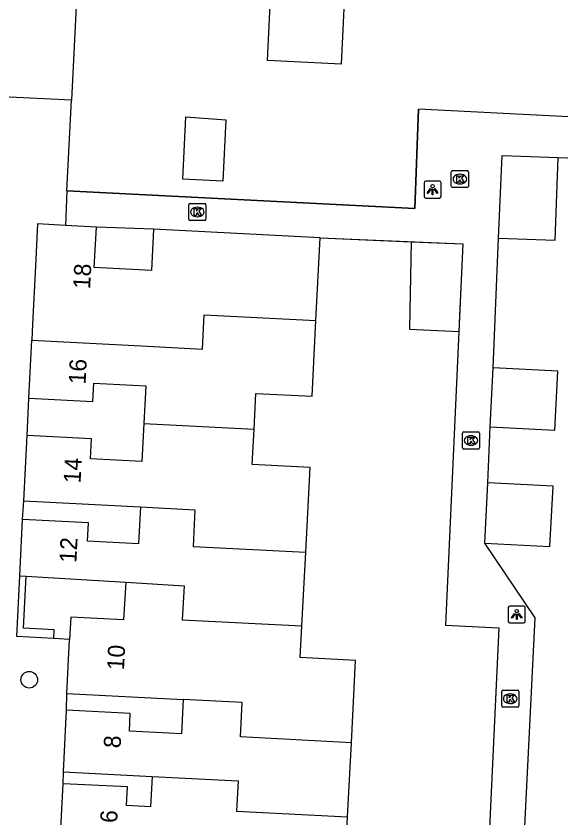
# Model space of a CAD drawing. Extents: x 162990 to 165007, y 383433 to 384336.
# Drawn here: x 164464.46 to 164496.47, y 383792.95 to 383840 of the extents above; entities that cross this region are included whole.
import ezdxf

# ---------------------------------------------------------------- set-up
doc = ezdxf.new("R2010")
doc.units = 0
for name, color, linetype in [('IMGEO_Boom', 7, 'Continuous'), ('IMGEO_Kolk', 7, 'Continuous'), ('IMGEO_Lichtpunt', 7, 'Continuous'), ('IMGEO_Muur', 7, 'Continuous'), ('IMGEO_Pand', 7, 'Continuous'), ('IMGEO_Pand_nummerreeks', 7, 'Continuous'), ('IMGEO_Voetpad_open', 7, 'Continuous')]:
    doc.layers.add(name, color=color, linetype=linetype)

msp = doc.modelspace()

# ---------------------------------------------------------------- linework, layer by layer
at = {"layer": 'IMGEO_Boom'}
msp.add_circle((164465.239, 383801.064), 0.489, dxfattribs=at)
at = {"layer": 'IMGEO_Kolk'}
for p, q in [((164490.028, 383830.011), (164490.028, 383830.863)), ((164490.103, 383830.937), (164490.955, 383830.937)), ((164491.029, 383830.863), (164491.029, 383830.011)), ((164490.516, 383830.717), (164490.541, 383830.717)), ((164490.955, 383829.937), (164490.103, 383829.937)), ((164490.539, 383830.157), (164490.514, 383830.157)), ((164474.612, 383828.079), (164474.612, 383828.931)), ((164474.687, 383829.005), (164475.539, 383829.005)), ((164475.613, 383828.931), (164475.613, 383828.079)), ((164475.1, 383828.785), (164475.125, 383828.785)), ((164475.539, 383828.005), (164474.687, 383828.005)), ((164475.123, 383828.225), (164475.098, 383828.225)), ((164490.682, 383814.674), (164490.682, 383815.526)), ((164490.757, 383815.6), (164491.609, 383815.6)), ((164491.17, 383815.38), (164491.195, 383815.38)), ((164491.683, 383815.526), (164491.683, 383814.674)), ((164491.193, 383814.82), (164491.168, 383814.82)), ((164491.609, 383814.6), (164490.757, 383814.6)), ((164492.987, 383799.523), (164492.987, 383800.375)), ((164493.062, 383800.449), (164493.914, 383800.449)), ((164493.475, 383800.229), (164493.5, 383800.229)), ((164493.988, 383800.375), (164493.988, 383799.523)), ((164493.914, 383799.449), (164493.062, 383799.449)), ((164493.498, 383799.669), (164493.473, 383799.669))]:
    msp.add_line(p, q, dxfattribs=at)
for points in [[(164490.028, 383830.011), (164490.028, 383830.863)], [(164490.103, 383830.937), (164490.955, 383830.937)], [(164491.029, 383830.863), (164491.029, 383830.011)], [(164490.349, 383830.637), (164490.472, 383830.637), (164490.472, 383830.486), (164490.602, 383830.637), (164490.766, 383830.637), (164490.62, 383830.486), (164490.773, 383830.237), (164490.621, 383830.237), (164490.536, 383830.401), (164490.472, 383830.334), (164490.472, 383830.237), (164490.349, 383830.237), (164490.349, 383830.637)], [(164490.955, 383829.937), (164490.103, 383829.937)], [(164474.612, 383828.079), (164474.612, 383828.931)], [(164474.687, 383829.005), (164475.539, 383829.005)], [(164475.613, 383828.931), (164475.613, 383828.079)], [(164474.933, 383828.705), (164475.056, 383828.705), (164475.056, 383828.554), (164475.186, 383828.705), (164475.35, 383828.705), (164475.204, 383828.554), (164475.357, 383828.305), (164475.205, 383828.305), (164475.12, 383828.469), (164475.056, 383828.402), (164475.056, 383828.305), (164474.933, 383828.305), (164474.933, 383828.705)], [(164475.539, 383828.005), (164474.687, 383828.005)], [(164490.682, 383814.674), (164490.682, 383815.526)], [(164490.757, 383815.6), (164491.609, 383815.6)], [(164491.003, 383815.3), (164491.126, 383815.3), (164491.126, 383815.149), (164491.256, 383815.3), (164491.42, 383815.3), (164491.274, 383815.149), (164491.427, 383814.9), (164491.275, 383814.9), (164491.19, 383815.064), (164491.126, 383814.997), (164491.126, 383814.9), (164491.003, 383814.9), (164491.003, 383815.3)], [(164491.683, 383815.526), (164491.683, 383814.674)], [(164491.609, 383814.6), (164490.757, 383814.6)], [(164492.987, 383799.523), (164492.987, 383800.375)], [(164493.062, 383800.449), (164493.914, 383800.449)], [(164493.988, 383800.375), (164493.988, 383799.523)], [(164493.308, 383800.149), (164493.431, 383800.149), (164493.431, 383799.998), (164493.561, 383800.149), (164493.725, 383800.149), (164493.579, 383799.998), (164493.732, 383799.749), (164493.58, 383799.749), (164493.495, 383799.913), (164493.431, 383799.846), (164493.431, 383799.749), (164493.308, 383799.749), (164493.308, 383800.149)], [(164493.914, 383799.449), (164493.062, 383799.449)]]:
    msp.add_lwpolyline(points, dxfattribs=at)
for centre, start, end in [((164490.105, 383830.861), 91.552, 178.448), ((164490.105, 383830.861), 91.552, 178.448), ((164490.953, 383830.861), 1.552, 88.448), ((164490.953, 383830.861), 1.552, 88.448), ((164490.105, 383830.013), 181.552, 268.448), ((164490.105, 383830.013), 181.552, 268.448), ((164490.953, 383830.013), 271.552, 358.448), ((164490.953, 383830.013), 271.552, 358.448), ((164474.689, 383828.929), 91.552, 178.448), ((164474.689, 383828.929), 91.552, 178.448), ((164475.537, 383828.929), 1.552, 88.448), ((164475.537, 383828.929), 1.552, 88.448), ((164474.689, 383828.081), 181.552, 268.448), ((164474.689, 383828.081), 181.552, 268.448), ((164475.537, 383828.081), 271.552, 358.448), ((164475.537, 383828.081), 271.552, 358.448), ((164490.759, 383815.524), 91.552, 178.448), ((164490.759, 383815.524), 91.552, 178.448), ((164491.607, 383815.524), 1.552, 88.448), ((164491.607, 383815.524), 1.552, 88.448), ((164490.759, 383814.676), 181.552, 268.448), ((164490.759, 383814.676), 181.552, 268.448), ((164491.607, 383814.676), 271.552, 358.448), ((164491.607, 383814.676), 271.552, 358.448), ((164493.064, 383800.373), 91.552, 178.448), ((164493.064, 383800.373), 91.552, 178.448), ((164493.912, 383800.373), 1.552, 88.448), ((164493.912, 383800.373), 1.552, 88.448), ((164493.064, 383799.525), 181.552, 268.448), ((164493.064, 383799.525), 181.552, 268.448), ((164493.912, 383799.525), 271.552, 358.448), ((164493.912, 383799.525), 271.552, 358.448)]:
    msp.add_arc(centre, 0.0765, start, end, dxfattribs=at)
for centre, major_axis, ratio, start_param, end_param in [((164490.515, 383830.437), (-0.387, 0.002), 0.722429, 4.712389, 7.853982), ((164490.54, 383830.437), (-0.39, 0.002), 0.717154, 1.570796, 4.712389), ((164475.099, 383828.505), (-0.387, 0.002), 0.722429, 4.712389, 7.853982), ((164475.124, 383828.505), (-0.39, 0.002), 0.717154, 1.570796, 4.712389), ((164491.169, 383815.1), (-0.387, 0.002), 0.722429, 4.712389, 7.853982), ((164491.194, 383815.1), (-0.39, 0.002), 0.717154, 1.570796, 4.712389), ((164493.474, 383799.949), (-0.387, 0.002), 0.722429, 4.712389, 7.853982), ((164493.499, 383799.949), (-0.39, 0.002), 0.717154, 1.570796, 4.712389)]:
    msp.add_ellipse(centre, major_axis=major_axis, ratio=ratio, start_param=start_param, end_param=end_param, dxfattribs=at)
at = {"layer": 'IMGEO_Lichtpunt'}
for p, q in [((164488.427, 383830.225), (164488.427, 383829.418)), ((164488.427, 383830.225), (164488.427, 383829.418)), ((164489.329, 383830.32), (164488.521, 383830.32)), ((164489.329, 383830.32), (164488.521, 383830.32)), ((164489.423, 383829.418), (164489.423, 383830.225)), ((164489.423, 383829.418), (164489.423, 383830.225)), ((164488.521, 383829.324), (164489.329, 383829.324)), ((164488.521, 383829.324), (164489.329, 383829.324)), ((164493.372, 383805.294), (164493.372, 383804.487)), ((164493.372, 383805.294), (164493.372, 383804.487)), ((164494.274, 383805.389), (164493.466, 383805.389)), ((164494.274, 383805.389), (164493.466, 383805.389)), ((164494.368, 383804.487), (164494.368, 383805.294)), ((164494.368, 383804.487), (164494.368, 383805.294)), ((164493.466, 383804.393), (164494.274, 383804.393)), ((164493.466, 383804.393), (164494.274, 383804.393))]:
    msp.add_line(p, q, dxfattribs=at)
for points in [[(164488.801, 383829.889), (164488.84, 383829.861), (164488.652, 383829.599), (164488.614, 383829.626), (164488.801, 383829.889)], [(164489.013, 383829.861), (164489.051, 383829.888), (164489.238, 383829.626), (164489.199, 383829.598), (164489.013, 383829.861)], [(164488.903, 383829.841), (164488.95, 383829.841), (164488.95, 383829.519), (164488.903, 383829.519), (164488.903, 383829.841)], [(164493.746, 383804.958), (164493.785, 383804.93), (164493.597, 383804.668), (164493.559, 383804.695), (164493.746, 383804.958)], [(164493.958, 383804.93), (164493.996, 383804.957), (164494.183, 383804.695), (164494.144, 383804.667), (164493.958, 383804.93)], [(164493.848, 383804.91), (164493.895, 383804.91), (164493.895, 383804.588), (164493.848, 383804.588), (164493.848, 383804.91)]]:
    msp.add_lwpolyline(points, dxfattribs=at)
for centre in [(164488.926, 383830.023), (164493.871, 383805.092)]:
    msp.add_circle(centre, 0.0994, dxfattribs=at)
for centre, start, end in [((164488.521, 383830.225), 90, 180), ((164488.521, 383830.225), 90, 180), ((164489.329, 383830.225), 0, 90), ((164489.329, 383830.225), 0, 90), ((164488.521, 383829.418), 180, 270), ((164488.521, 383829.418), 180, 270), ((164489.329, 383829.418), 270, 0), ((164489.329, 383829.418), 270, 360), ((164493.466, 383805.294), 90, 180), ((164493.466, 383805.294), 90, 180), ((164494.274, 383805.294), 0, 90), ((164494.274, 383805.294), 0, 90), ((164493.466, 383804.487), 180, 270), ((164493.466, 383804.487), 180, 270), ((164494.274, 383804.487), 270, 0), ((164494.274, 383804.487), 270, 360)]:
    msp.add_arc(centre, 0.0946, start, end, dxfattribs=at)
at = {"layer": 'IMGEO_Muur'}
for points in [[(164467.442, 383829.749), (164487.891, 383828.72), (164488.106, 383834.549)], [(164482.324, 383826.996), (164490.702, 383826.631), (164490.492, 383821.986)], [(164466.675, 383803.486), (164464.501, 383803.598), (164464.678, 383807.155)], [(164466.675, 383803.486), (164466.701, 383803.997), (164464.908, 383804.089), (164465.065, 383807.132)]]:
    msp.add_lwpolyline(points, dxfattribs=at)
at = {"layer": 'IMGEO_Pand'}
for points in [[(164484.092, 383841.249), (164483.76, 383841.265), (164483.559, 383837.188), (164479.233, 383837.401), (164479.436, 383841.479)], [(164476.79, 383833.913), (164476.611, 383830.32), (164474.26, 383830.437), (164474.442, 383834.089), (164476.79, 383833.913)], [(164492.801, 383826.964), (164493.007, 383831.822), (164496.297, 383831.704)], [(164492.801, 383826.964), (164496.123, 383826.846), (164496.297, 383831.704)], [(164467.361, 383827.718), (164465.722, 383827.803), (164465.595, 383825.336), (164465.42, 383821.932), (164465.392, 383820.979)], [(164469.195, 383827.624), (164467.361, 383827.718)], [(164472.541, 383827.499), (164472.416, 383825.072), (164469.051, 383825.245), (164469.195, 383827.624)], [(164482.324, 383826.996), (164472.541, 383827.499)], [(164482.074, 383822.138), (164482.324, 383826.996)], [(164487.671, 383826.763), (164487.572, 383821.695), (164487.568, 383821.624), (164490.47, 383821.493)], [(164487.671, 383826.763), (164490.702, 383826.631), (164490.47, 383821.493)], [(164465.392, 383820.979), (164472.175, 383820.63), (164475.413, 383820.463), (164475.509, 383822.478), (164482.074, 383822.138)], [(164478.441, 383815.758), (164478.55, 383817.866), (164481.846, 383817.697), (164482.074, 383822.138)], [(164465.217, 383817.583), (164465.392, 383820.979)], [(164492.3, 383815.903), (164496.099, 383815.707), (164496.278, 383819.176), (164492.479, 383819.372)], [(164492.3, 383815.903), (164492.479, 383819.372)], [(164465.217, 383817.583), (164468.973, 383817.39), (164469.028, 383818.473), (164472.088, 383818.316), (164471.973, 383816.092)], [(164471.973, 383816.092), (164471.859, 383813.872), (164468.829, 383814.027), (164468.89, 383815.204), (164465.109, 383815.398)], [(164471.973, 383816.092), (164478.441, 383815.758)], [(164481.476, 383808.539), (164481.732, 383813.514), (164478.335, 383813.689), (164478.441, 383815.758)], [(164464.911, 383811.553), (164465.109, 383815.398)], [(164491.994, 383809.075), (164495.821, 383808.878), (164496.004, 383812.421), (164492.176, 383812.618)], [(164491.994, 383809.075), (164492.176, 383812.618)], [(164464.911, 383811.553), (164471.769, 383811.2)], [(164471.769, 383811.2), (164471.658, 383809.043), (164468.653, 383809.198), (164468.708, 383810.271), (164464.849, 383810.47)], [(164471.769, 383811.2), (164474.967, 383811.035), (164474.866, 383808.88), (164481.476, 383808.539)], [(164464.678, 383807.155), (164464.849, 383810.47)], [(164481.254, 383804.216), (164481.476, 383808.539)], [(164464.678, 383807.155), (164465.065, 383807.132)], [(164465.065, 383807.132), (164470.904, 383806.783)], [(164470.904, 383806.783), (164470.779, 383804.578), (164467.677, 383804.738), (164467.609, 383803.423)], [(164470.904, 383806.783), (164474.33, 383806.578), (164474.227, 383804.581), (164481.254, 383804.216)], [(164484.155, 383797.368), (164484.403, 383802.192), (164481.158, 383802.359), (164481.254, 383804.216)], [(164467.447, 383800.264), (164467.609, 383803.423)], [(164467.447, 383800.264), (164474.279, 383799.912)], [(164474.279, 383799.912), (164474.175, 383797.892), (164471.117, 383798.049), (164471.171, 383799.091), (164467.434, 383799.283)], [(164484.155, 383797.368), (164477.644, 383797.709), (164477.748, 383799.73), (164474.279, 383799.912)], [(164467.247, 383795.658), (164467.434, 383799.283)], [(164483.931, 383793.023), (164484.155, 383797.368)], [(164467.247, 383795.658), (164472.456, 383795.39)], [(164472.456, 383795.39), (164472.365, 383793.609), (164470.948, 383793.682), (164471.004, 383794.77), (164467.231, 383794.964)], [(164472.456, 383795.39), (164474.007, 383795.31), (164477.511, 383795.128), (164477.419, 383793.353), (164483.931, 383793.023)], [(164467.037, 383791.21), (164467.231, 383794.964)], [(164483.687, 383788.274), (164483.931, 383793.023)]]:
    msp.add_lwpolyline(points, dxfattribs=at)
at = {"layer": 'IMGEO_Voetpad_open'}
for points in [[(164468.388, 383848.483), (164467.711, 383835.068)], [(164467.711, 383835.068), (164463.666, 383835.272)], [(164467.442, 383829.749), (164467.711, 383835.068)], [(164518.523, 383832.968), (164500, 383833.931), (164488.106, 383834.549), (164487.891, 383828.72), (164467.442, 383829.749)], [(164496.297, 383831.704), (164500, 383831.572), (164501.724, 383831.51)], [(164467.442, 383829.749), (164467.361, 383827.718)], [(164472.541, 383827.499), (164469.195, 383827.624)], [(164482.324, 383826.996), (164487.671, 383826.763)], [(164492.479, 383819.372), (164492.801, 383826.964)], [(164490.47, 383821.493), (164489.689, 383804.263), (164492.818, 383804.115), (164491.616, 383778.506), (164489.656, 383778.574), (164489.35, 383771.704), (164487.711, 383771.764), (164486.682, 383749.35)], [(164465.109, 383815.398), (164465.217, 383817.583)], [(164492.176, 383812.618), (164492.3, 383815.903)], [(164464.849, 383810.47), (164464.911, 383811.553)], [(164488.667, 383743.403), (164488.973, 383750), (164489.842, 383768.755), (164491.362, 383768.605), (164491.668, 383775.196), (164493.488, 383775.067), (164494.946, 383804.692), (164491.994, 383809.075)], [(164467.609, 383803.423), (164466.675, 383803.486)], [(164467.434, 383799.283), (164467.447, 383800.264)], [(164467.231, 383794.964), (164467.247, 383795.658)]]:
    msp.add_lwpolyline(points, dxfattribs=at)

# ---------------------------------------------------------------- texts
at = {"layer": 'IMGEO_Pand_nummerreeks'}
for s, rotation, p in [('18', 87.0552, (164468.81, 383823.971)), ('16', 87.0501, (164468.543, 383818.378)), ('14', 87.0521, (164468.248, 383812.572)), ('12', 87.0471, (164468.002, 383807.906)), ('10', 87.0571, (164470.8, 383801.601)), ('8', 87.0469, (164470.602, 383797.031)), ('6', 87.0417, (164470.395, 383792.643))]:
    msp.add_text(s, height=1, rotation=rotation, dxfattribs=at).set_placement(p)

doc.saveas('drawing.dxf')
